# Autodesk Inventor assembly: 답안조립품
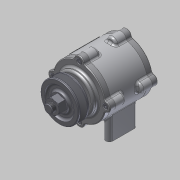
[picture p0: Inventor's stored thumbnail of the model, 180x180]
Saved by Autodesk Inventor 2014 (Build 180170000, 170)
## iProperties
Created: 2015-03
Part Number: 답안조립품
Document SubType Name: Assembly
Designer: MYHOME
Author: MYHOME
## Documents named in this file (11)
- C:\Documents and Settings\MYHOME\바탕 화면\450306V1017\답안조립품.iam
- C:\Documents and Settings\MYHOME\바탕 화면\450306V1017\본체.ipt
- C:\Documents and Settings\MYHOME\바탕 화면\450306V1017\커버.ipt
- C:\Documents and Settings\MYHOME\바탕 화면\450306V1017\커버2.ipt
- C:\Documents and Settings\MYHOME\바탕 화면\450306V1017\M 4 x 12.ipt
- C:\Documents and Settings\MYHOME\바탕 화면\450306V1017\오일실.ipt
- C:\Documents and Settings\MYHOME\바탕 화면\450306V1017\베어링 6204.ipt
- C:\Documents and Settings\MYHOME\바탕 화면\450306V1017\축.ipt
- C:\Documents and Settings\MYHOME\바탕 화면\450306V1017\키(4 x 4 x 12).ipt
- C:\Documents and Settings\MYHOME\바탕 화면\450306V1017\V벨트풀리.ipt
- C:\Documents and Settings\MYHOME\바탕 화면\450306V1017\너트 M12x1.25.ipt
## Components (14 placed, 6 different names)
1. KS B 2804 D D - 20 32 8:1
2. KS B 2023 6204 - 20 x 47 x 14:1 — 각도:3
3. KS B 2023 6204 - 20 x 47 x 14:2 — 각도:2
4. KS B 1311 (I) 4 x 4 x 12:1
5. 그루브 풀리1:1
6. KS B 1012 클래스 1 일반 - 미터 M12x1.25:1 — 각도:4
7. KS B 1003 - 미터 M 4 x 12:1
8. KS B 1003 - 미터 M 4 x 12:2
9. KS B 1003 - 미터 M 4 x 12:3
10. KS B 1003 - 미터 M 4 x 12:4
11. KS B 1003 - 미터 M 4 x 12:5
12. KS B 1003 - 미터 M 4 x 12:6
13. KS B 1003 - 미터 M 4 x 12:7
14. KS B 1003 - 미터 M 4 x 12:8
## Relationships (3: Angle 3)
- 각도:2 [Angle]: KS B 2023 6204 - 20 x 47 x 14:2
- 각도:3 [Angle]: KS B 2023 6204 - 20 x 47 x 14:1
- 각도:4 [Angle]: KS B 1012 클래스 1 일반 - 미터 M12x1.25:1
